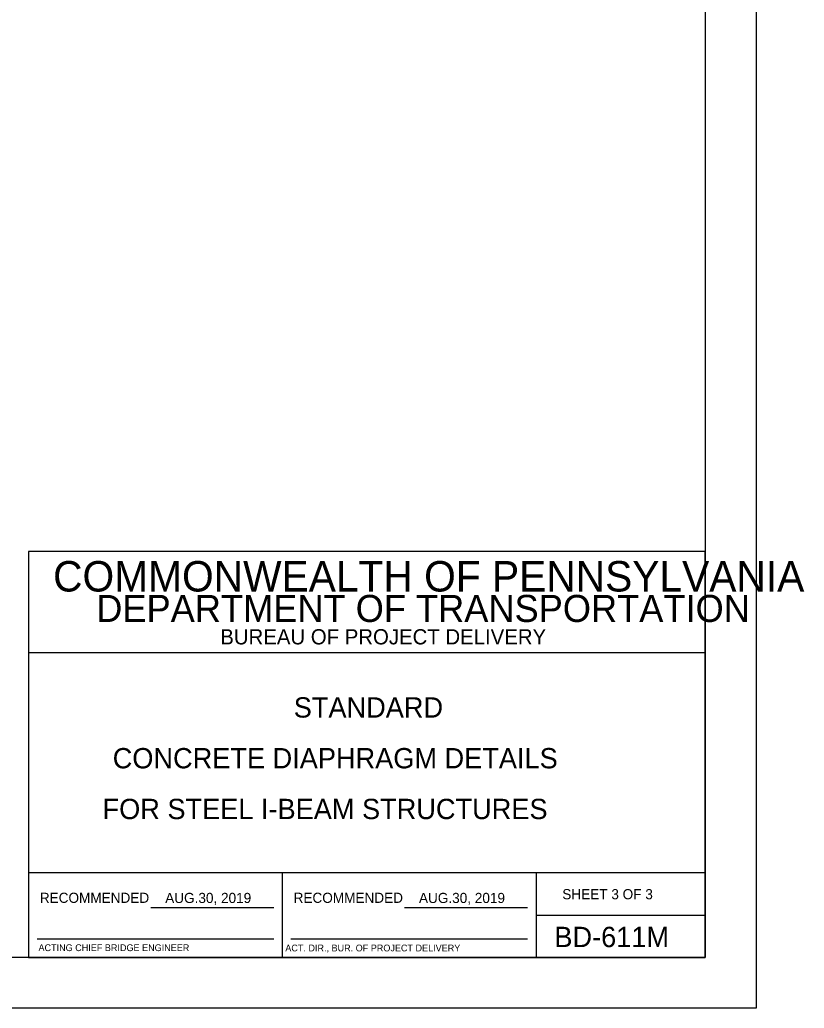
# Model space of a CAD drawing. Extents: x 640009 to 641706, y 298547 to 299735.
# Drawn here: x 640632.9 to 640864.7, y 298547.2 to 298839.2 of the extents above; entities that cross this region are included whole.
import ezdxf

# ---------------------------------------------------------------- set-up
doc = ezdxf.new("R2010")
doc.units = 0
doc.layers.add('1', color=7, linetype='Continuous')
doc.layers.add('PLT-BNDY', color=7, linetype='Continuous')

msp = doc.modelspace()

# ---------------------------------------------------------------- linework, layer by layer
at = {"layer": '1'}
for p, q in [((640835.47, 299126.17), (640835.47, 298562.17)), ((640835.47, 299126.17), (640835.47, 298562.17)), ((640835.47, 298682.17), (640635.47, 298682.17)), ((640635.47, 298682.17), (640635.47, 298562.17)), ((640835.47, 298682.17), (640635.47, 298682.17)), ((640635.47, 298682.17), (640635.47, 298562.17)), ((640835.47, 298562.17), (640835.47, 298682.17)), ((640835.47, 298562.17), (640835.47, 298682.17)), ((640835.47, 298652.17), (640635.47, 298652.17)), ((640835.47, 298652.17), (640635.47, 298652.17)), ((640835.47, 298587.17), (640635.47, 298587.17)), ((640835.47, 298587.17), (640635.47, 298587.17)), ((640710.47, 298562.17), (640710.47, 298587.17)), ((640785.47, 298587.17), (640785.47, 298562.17)), ((640785.47, 298587.17), (640785.47, 298562.17)), ((640671.56, 298576.89), (640707.97, 298576.89)), ((640746.56, 298576.89), (640782.97, 298576.89)), ((640785.47, 298574.67), (640835.47, 298574.67)), ((640785.47, 298574.67), (640835.47, 298574.67)), ((640637.97, 298567.67), (640707.97, 298567.67)), ((640712.97, 298567.67), (640782.97, 298567.67)), ((640835.47, 298562.17), (640049.47, 298562.17)), ((640835.47, 298562.17), (640049.47, 298562.17)), ((640635.47, 298562.17), (640835.47, 298562.17)), ((640635.47, 298562.17), (640835.47, 298562.17))]:
    msp.add_line(p, q, dxfattribs=at)
at = {"layer": 'PLT-BNDY'}
msp.add_lwpolyline([(640009.47, 299141.17), (640850.47, 299141.17), (640850.47, 298547.17), (640009.47, 298547.17)], close=True, dxfattribs=at)

# ---------------------------------------------------------------- texts
at = {"layer": '1'}
for s, height, p in [('COMMONWEALTH OF PENNSYLVANIA', 9, (640642.72, 298670.3)), ('DEPARTMENT OF TRANSPORTATION', 8.0002, (640655.47, 298661.3)), ('BUREAU OF PROJECT DELIVERY', 4.5, (640692.13, 298654.67)), ('STANDARD', 6, (640713.84, 298633.05)), ('CONCRETE DIAPHRAGM DETAILS', 6, (640660.34, 298618.05)), ('FOR STEEL I-BEAM STRUCTURES', 6, (640657.34, 298603.05)), ('SHEET 3 OF 3', 3, (640793.21, 298579.37)), ('RECOMMENDED', 3, (640638.8, 298578.3)), ('AUG.30, 2019', 3, (640675.85, 298578.26)), ('RECOMMENDED', 3, (640713.8, 298578.3)), ('AUG.30, 2019', 3, (640750.85, 298578.26)), ('BD-611M', 6, (640790.86, 298565.24)), ('ACTING CHIEF BRIDGE ENGINEER', 2.0002, (640638.4, 298564.05)), (' ACT. DIR., BUR. OF PROJECT DELIVERY', 2.0002, (640710.6, 298563.97))]:
    msp.add_text(s, height=height, dxfattribs=at).set_placement(p)

doc.saveas('drawing.dxf')
